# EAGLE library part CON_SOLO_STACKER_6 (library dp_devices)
SOLO Staggard Stocker Mfr no: 009188006020062 009188006020062
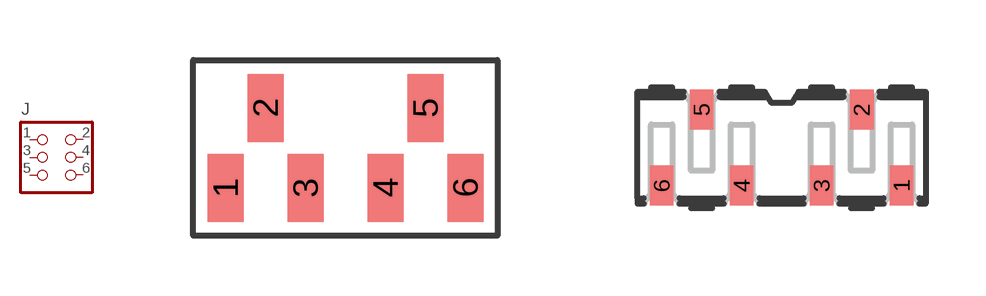
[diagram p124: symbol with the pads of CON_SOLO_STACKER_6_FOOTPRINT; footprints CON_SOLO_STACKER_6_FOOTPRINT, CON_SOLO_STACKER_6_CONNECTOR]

Designator prefix J

## CON_SOLO_STACKER_6-FOOTPRINT  [CON_SOLO_STACKER_6_FOOTPRINT]
1  1  pas
2  2  pas
3  3  pas
4  4  pas
5  5  pas
6  6  pas

## CON_SOLO_STACKER_6-CONNECTOR  [CON_SOLO_STACKER_6_CONNECTOR]
Pads as for CON_SOLO_STACKER_6_FOOTPRINT

## Footprint CON_SOLO_STACKER_6_FOOTPRINT (pad centres in mm)
SOLO Staggard Stocker Mfr no: 009188006020062 009188006020062
smd 0.9 x 1.7: 1 -3,-1; 2 -2,1; 3 -1,-1; 4 1,-1; 5 2,1; 6 3,-1

## Footprint CON_SOLO_STACKER_6_CONNECTOR (pad centres in mm)
SOLO Staggard Stocker Mfr no: 009188006020062 009188006020062
smd 0.6 x 1: 1 3,-0.95; 2 2,0.95; 3 1,-0.95; 4 -1,-0.95; 5 -2,0.95; 6 -3,-0.95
